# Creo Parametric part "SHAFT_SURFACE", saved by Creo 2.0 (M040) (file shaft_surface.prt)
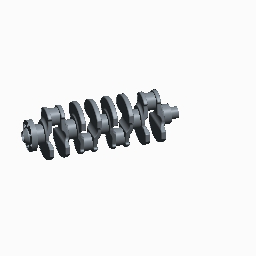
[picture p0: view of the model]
Units: millimeter Kilogram Sec (mmKs); MM, KILOGRAM, SECS

Created from: INLBS_PART_SOLID.PRT

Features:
  1. datum plane "RIGHT"
  2. datum plane "TOP"
  3. datum plane "FRONT"
  4. coordinate system
  5. sketch "Sketch 1"
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
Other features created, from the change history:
  feature "Extrude 1"
  feature "Extrude 2"
  feature "Merge 1"
  datum plane "DTM1"
  datum plane "DTM2"
  extruded cut "Extrude 3"
  sketch "Sketch 2"
  fill "Fill 1"
  feature "Merge 2"
  feature "Extrude 4"
  feature "Merge 3"
  feature "Extrude 5"
  feature "Merge 4"
  sketch "Sketch 3"
  fill "Fill 2"
  feature "Merge 5"
  round "Round 1"
  round "Round 2"
  round "Round 3" (2 times)
  round "Round 4"
  round "Round 5"
  round "Round 6"
  round "Round 7"
  datum plane "DTM3"
  datum axis "A_1"
  feature "Extrude 6"
  feature "Merge 6"
  datum plane "MID"
  mirror "Mirror 1"
  feature "Merge 7"
  feature "Copy 1"
  patch "Solidify 1"
  patch "Solidify 2"
  patch "Solidify 3"
  patch "Solidify 4"
  extrusion "Extrude 7"
  extrusion "Extrude 8"
  extrusion "Extrude 9"
  pattern "Pattern 1"
  extrusion "Extrude 9 [2]"
  extrusion "Extrude 9 [3]"
  extrusion "Extrude 9 [4]"
  extrusion "Extrude 10"
  extrusion "Extrude 11"
  chamfer "Chamfer 1"
  hole "Hole 1"
  pattern "Pattern 2"
  hole "Hole 1 [2]"
  hole "Hole 1 [3]"
  hole "Hole 1 [4]"
  hole "Hole 1 [5]"
  hole "Hole 1 [6]"

Other named items: COPIED_GROUP, COPIED_GROUP_1, COPIED_GROUP_2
